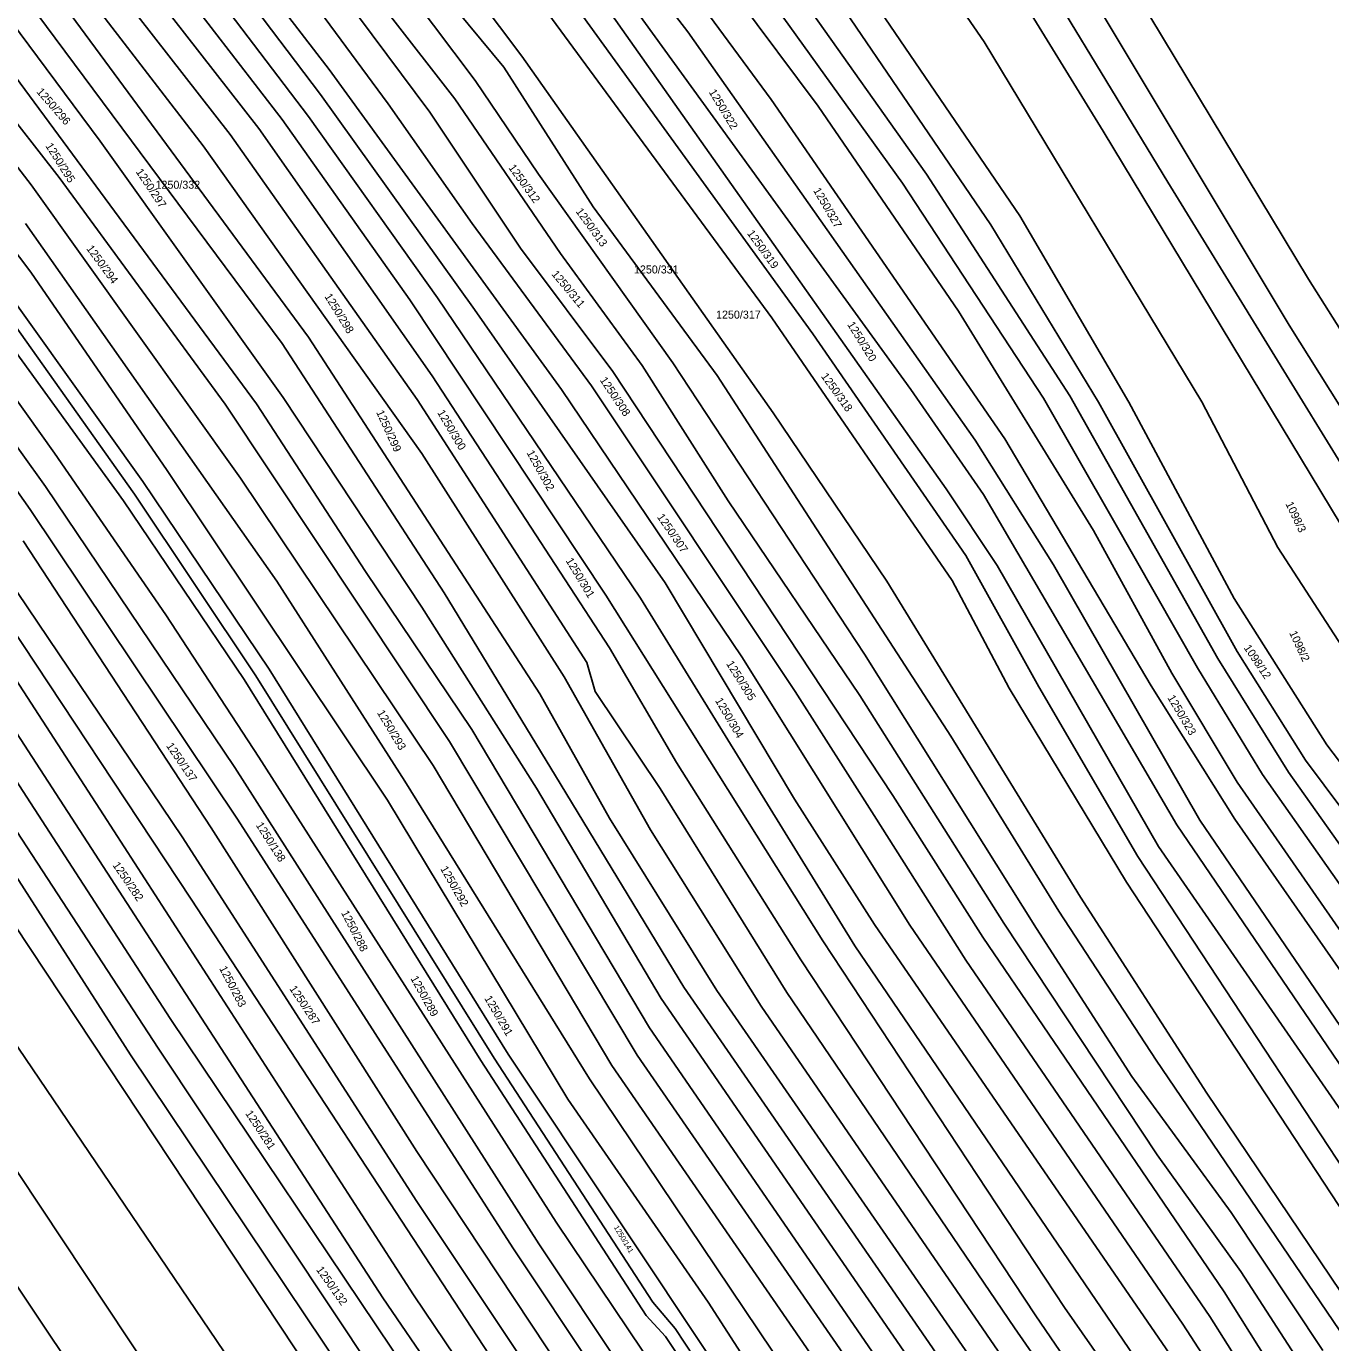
# Model space of a CAD drawing. Extents: x -580630 to -576196, y -1189024 to -1183567.
# Drawn here: x -576696.2 to -576419.3, y -1187029.9 to -1186750.3 of the extents above; entities that cross this region are included whole.
import ezdxf

# ---------------------------------------------------------------- set-up
doc = ezdxf.new("R2010")
doc.units = 0
for name, color, linetype in [('Vrstva 1', 7, 'Continuous'), ('Vrstva 13', 7, 'Continuous'), ('Vrstva 18', 7, 'Continuous'), ('Vrstva 6', 7, 'Continuous')]:
    doc.layers.add(name, color=color, linetype=linetype)

msp = doc.modelspace()

# ---------------------------------------------------------------- linework, layer by layer
at = {"layer": 'Vrstva 1'}
for p, q in [((-576556.97, -1186708.4), (-576505.07, -1186781.72)), ((-576505.07, -1186781.72), (-576474.68, -1186828.83)), ((-576474.68, -1186828.83), (-576443.27, -1186884.64)), ((-576443.27, -1186884.64), (-576428.26, -1186908.73)), ((-576428.26, -1186908.73), (-576403.1, -1186944.3))]:
    msp.add_line(p, q, dxfattribs=at)
at = {"layer": 'Vrstva 13'}
for p in [(-576479.83, -1186711.34), (-576349.23, -1186922.92)]:
    msp.add_line(p, (-576423.97, -1186804.04), dxfattribs=at)
at = {"layer": 'Vrstva 6'}
for p, q in [((-576613.29, -1186682.63), (-576508.42, -1186827.47)), ((-576534.36, -1186692.75), (-576492.88, -1186753.59)), ((-576622.55, -1186696.97), (-576537.97, -1186812.23)), ((-576546.23, -1186701.09), (-576485.28, -1186790.58)), ((-576591.05, -1186756.63), (-576630.49, -1186703.86)), ((-576491.41, -1186792.52), (-576551.36, -1186704.52)), ((-576561.77, -1186711.76), (-576510.17, -1186783.65)), ((-576647.75, -1186718.6), (-576610.52, -1186768.55)), ((-576672.45, -1186721.96), (-576636.33, -1186769.44)), ((-576666.06, -1186722.05), (-576633.75, -1186764.79)), ((-576661.74, -1186720.73), (-576631.94, -1186759.47)), ((-576652.19, -1186722.22), (-576619.42, -1186766.8)), ((-576555.75, -1186751.48), (-576577.57, -1186723.34)), ((-576675.89, -1186726.07), (-576641.91, -1186770.11)), ((-576479.93, -1186727.4), (-576428.06, -1186813.81)), ((-576677.23, -1186732.97), (-576646.86, -1186772.02)), ((-576553.73, -1186732.94), (-576528.12, -1186767.27)), ((-576453.84, -1186783.39), (-576485.53, -1186731.29)), ((-576681.61, -1186736.43), (-576652.92, -1186773.31)), ((-576587.25, -1186735.49), (-576529.24, -1186815.62)), ((-576467.57, -1186772.6), (-576490.49, -1186735.3)), ((-576594.84, -1186759.02), (-576612.67, -1186737.47)), ((-576559.28, -1186736.98), (-576538.08, -1186765.85)), ((-576686.36, -1186739.65), (-576658.67, -1186775.72)), ((-576615.81, -1186741.99), (-576600.9, -1186761.8)), ((-576696.02, -1186744.83), (-576641.92, -1186817.73)), ((-576701.41, -1186746.62), (-576680.56, -1186774.73)), ((-576688.69, -1186745.25), (-576636.34, -1186816.34)), ((-576619.43, -1186747.49), (-576605.22, -1186765.7)), ((-576572.79, -1186746.71), (-576500.9, -1186848.56)), ((-576715.25, -1186749.11), (-576689.28, -1186782.4)), ((-576708.39, -1186747.72), (-576647.39, -1186830.49)), ((-576719.41, -1186752.77), (-576695.21, -1186783.97)), ((-576494.76, -1186838.24), (-576555.75, -1186751.48)), ((-576492.88, -1186753.59), (-576446.62, -1186830.11)), ((-576591.05, -1186756.63), (-576537.67, -1186832.45)), ((-576727.86, -1186759.52), (-576695.31, -1186802.52)), ((-576631.94, -1186759.47), (-576582.63, -1186827.47)), ((-576594.84, -1186759.02), (-576575.89, -1186788.67)), ((-576600.9, -1186761.8), (-576587.49, -1186781.76)), ((-576633.75, -1186764.79), (-576601.07, -1186810.5)), ((-576619.42, -1186766.8), (-576601.59, -1186792.17)), ((-576605.22, -1186765.7), (-576582.84, -1186798.6)), ((-576538.08, -1186765.85), (-576488.46, -1186837.95)), ((-576636.33, -1186769.44), (-576608.94, -1186808)), ((-576610.52, -1186768.55), (-576591.31, -1186797.45)), ((-576528.12, -1186767.27), (-576498.33, -1186810.85)), ((-576739.41, -1186772.11), (-576690.26, -1186841)), ((-576646.86, -1186772.02), (-576610.09, -1186824.59)), ((-576641.91, -1186770.11), (-576614.79, -1186808.4)), ((-576404.7, -1186876.84), (-576467.57, -1186772.6)), ((-576680.56, -1186774.73), (-576641.68, -1186829.18)), ((-576652.92, -1186773.31), (-576613.27, -1186829.57)), ((-576658.67, -1186775.72), (-576612.25, -1186841.03)), ((-576738.63, -1186783.42), (-576692.19, -1186848.05)), ((-576695.21, -1186783.97), (-576650.79, -1186846.3)), ((-576689.28, -1186782.4), (-576654.04, -1186830.6)), ((-576587.49, -1186781.76), (-576558.99, -1186821.8)), ((-576510.17, -1186783.65), (-576480.27, -1186829.33)), ((-576401.55, -1186868.57), (-576453.84, -1186783.39)), ((-576741.86, -1186787.12), (-576695.41, -1186852.99)), ((-576575.89, -1186788.67), (-576549.52, -1186824.52)), ((-576710.52, -1186792.35), (-576671.51, -1186847.01)), ((-576696.44, -1186792.22), (-576643.03, -1186868.21)), ((-576601.59, -1186792.17), (-576576.24, -1186826.72)), ((-576485.28, -1186790.58), (-576462.15, -1186830.15)), ((-576712.79, -1186793.93), (-576673.25, -1186849.73)), ((-576468.58, -1186830.13), (-576491.41, -1186792.52)), ((-576715.59, -1186795.88), (-576675.6, -1186851.14)), ((-576591.31, -1186797.45), (-576571.69, -1186823.66)), ((-576582.84, -1186798.6), (-576565.48, -1186822.38)), ((-576695.31, -1186802.52), (-576666.32, -1186844.69)), ((-576614.79, -1186808.4), (-576573.22, -1186871.14)), ((-576608.94, -1186808), (-576565.85, -1186871.82)), ((-576601.07, -1186810.5), (-576560.58, -1186868.57)), ((-576498.33, -1186810.85), (-576469.67, -1186857.4)), ((-576737.02, -1186812.88), (-576663.12, -1186922.52)), ((-576537.97, -1186812.23), (-576499.65, -1186868.02)), ((-576428.06, -1186813.81), (-576409.16, -1186844.09)), ((-576636.34, -1186816.34), (-576587.21, -1186892.15)), ((-576529.24, -1186815.62), (-576496.74, -1186862.75)), ((-576641.92, -1186817.73), (-576607.52, -1186870.67)), ((-576565.48, -1186822.38), (-576547.18, -1186851.13)), ((-576558.99, -1186821.8), (-576518.26, -1186883.69)), ((-576610.09, -1186824.59), (-576572.4, -1186882.36)), ((-576571.69, -1186823.66), (-576512.27, -1186913.69)), ((-576549.52, -1186824.52), (-576499.95, -1186901.11)), ((-576582.63, -1186827.47), (-576544.28, -1186884.24)), ((-576576.24, -1186826.72), (-576532.98, -1186891.59)), ((-576508.42, -1186827.47), (-576492.98, -1186849.76)), ((-576654.04, -1186830.6), (-576606.37, -1186902.22)), ((-576647.39, -1186830.49), (-576624.21, -1186866.12)), ((-576641.68, -1186829.18), (-576612.26, -1186873.73)), ((-576613.27, -1186829.57), (-576577.24, -1186885.49)), ((-576480.27, -1186829.33), (-576465.39, -1186855.28)), ((-576439.15, -1186883.1), (-576468.58, -1186830.13)), ((-576462.15, -1186830.15), (-576439.76, -1186871.85)), ((-576446.62, -1186830.11), (-576430.48, -1186861.01)), ((-576537.67, -1186832.45), (-576513.52, -1186868.21)), ((-576478.15, -1186864.72), (-576494.76, -1186838.24)), ((-576488.46, -1186837.95), (-576457.4, -1186890.42)), ((-576690.26, -1186841), (-576666.59, -1186875.31)), ((-576612.25, -1186841.03), (-576582, -1186888.49)), ((-576666.32, -1186844.69), (-576619.52, -1186914.69)), ((-576692.19, -1186848.05), (-576651.96, -1186907.77)), ((-576671.51, -1186847.01), (-576644.65, -1186886.91)), ((-576650.79, -1186846.3), (-576609.83, -1186907.35)), ((-576673.25, -1186849.73), (-576647.5, -1186888.27)), ((-576500.9, -1186848.56), (-576490.11, -1186864.82)), ((-576492.98, -1186849.76), (-576451.94, -1186919.97)), ((-576695.41, -1186852.99), (-576651.38, -1186918.74)), ((-576675.6, -1186851.14), (-576649.99, -1186889.07)), ((-576547.18, -1186851.13), (-576519.25, -1186892.44)), ((-576465.39, -1186855.28), (-576447.53, -1186886.57)), ((-576469.67, -1186857.4), (-576453.04, -1186887.69)), ((-576711.3, -1186860), (-576661.21, -1186935.74)), ((-576696.89, -1186859.62), (-576657.02, -1186920.57)), ((-576430.48, -1186861.01), (-576413.37, -1186887.43)), ((-576715.41, -1186862.97), (-576679.88, -1186917.85)), ((-576496.74, -1186862.75), (-576481.27, -1186890.65)), ((-576490.11, -1186864.82), (-576455.83, -1186924.53)), ((-576447.09, -1186918.98), (-576478.15, -1186864.72)), ((-576720.45, -1186866.31), (-576620.55, -1187020.4)), ((-576624.21, -1186866.12), (-576601.63, -1186899.67)), ((-576724.98, -1186869.58), (-576665.68, -1186961.07)), ((-576643.03, -1186868.21), (-576615.86, -1186910.69)), ((-576607.52, -1186870.67), (-576583.85, -1186909.5)), ((-576560.58, -1186868.57), (-576533.11, -1186914.46)), ((-576513.52, -1186868.21), (-576472.4, -1186935.3)), ((-576499.65, -1186868.02), (-576487.56, -1186890.9)), ((-576573.22, -1186871.14), (-576527.14, -1186944.61)), ((-576565.85, -1186871.82), (-576520.29, -1186945.68)), ((-576439.76, -1186871.85), (-576420.11, -1186902.97)), ((-576666.59, -1186875.31), (-576646.89, -1186905.55)), ((-576612.26, -1186873.73), (-576587.88, -1186912.15)), ((-576732.19, -1186878.22), (-576674.14, -1186968.77)), ((-576727.06, -1186877.22), (-576668.24, -1186967.37)), ((-576572.4, -1186882.36), (-576558.19, -1186906.7)), ((-576544.28, -1186884.24), (-576508.63, -1186941.28)), ((-576518.26, -1186883.69), (-576481.76, -1186941.93)), ((-576424.6, -1186906.19), (-576439.15, -1186883.1)), ((-576644.65, -1186886.91), (-576593.89, -1186968.68)), ((-576577.24, -1186885.49), (-576575.47, -1186891.62)), ((-576447.53, -1186886.57), (-576433.75, -1186909.28)), ((-576649.99, -1186889.07), (-576599.72, -1186969.97)), ((-576647.5, -1186888.27), (-576596.89, -1186969.49)), ((-576582, -1186888.49), (-576563.71, -1186921.02)), ((-576453.04, -1186887.69), (-576439.15, -1186910.91)), ((-576587.21, -1186892.15), (-576572.43, -1186918.51)), ((-576575.47, -1186891.62), (-576561.64, -1186912.25)), ((-576532.98, -1186891.59), (-576516.19, -1186917.96)), ((-576519.25, -1186892.44), (-576488.71, -1186940.84)), ((-576487.56, -1186890.9), (-576462.64, -1186932.11)), ((-576481.27, -1186890.65), (-576460.21, -1186926.68)), ((-576457.4, -1186890.42), (-576439.62, -1186918.74)), ((-576601.63, -1186899.67), (-576563.93, -1186963.08)), ((-576499.95, -1186901.11), (-576477.02, -1186938.27)), ((-576606.37, -1186902.22), (-576566.5, -1186968.88)), ((-576420.11, -1186902.97), (-576397.3, -1186933.05)), ((-576646.89, -1186905.55), (-576583.76, -1187004.36)), ((-576558.19, -1186906.7), (-576531.75, -1186948.6)), ((-576398.86, -1186940.88), (-576424.6, -1186906.19)), ((-576651.96, -1186907.77), (-576587.41, -1187008.97)), ((-576609.83, -1186907.35), (-576571.93, -1186971.05)), ((-576583.85, -1186909.5), (-576556.6, -1186954.42)), ((-576408.69, -1186944.93), (-576433.75, -1186909.28)), ((-576615.86, -1186910.69), (-576576.68, -1186973.9)), ((-576587.88, -1186912.15), (-576561.43, -1186956.81)), ((-576561.64, -1186912.25), (-576534.73, -1186955.58)), ((-576439.15, -1186910.91), (-576411.01, -1186951.43)), ((-576619.52, -1186914.69), (-576581.26, -1186978.2)), ((-576533.11, -1186914.46), (-576516.12, -1186941.13)), ((-576512.27, -1186913.69), (-576493.15, -1186943.79)), ((-576679.88, -1186917.85), (-576614.03, -1187019.76)), ((-576516.19, -1186917.96), (-576496.78, -1186948.72)), ((-576657.02, -1186920.57), (-576613.32, -1186989.34)), ((-576651.38, -1186918.74), (-576592.95, -1187009.79)), ((-576572.43, -1186918.51), (-576549.62, -1186955.14)), ((-576451.94, -1186919.97), (-576411.98, -1186978.75)), ((-576447.09, -1186918.98), (-576405.8, -1186979.52)), ((-576439.62, -1186918.74), (-576416.04, -1186952.56)), ((-576663.12, -1186922.52), (-576613.34, -1186999.97)), ((-576563.71, -1186921.02), (-576540.2, -1186958.46)), ((-576455.83, -1186924.53), (-576417.04, -1186980.67)), ((-576460.21, -1186926.68), (-576400.41, -1187017.72)), ((-576462.64, -1186932.11), (-576403.1, -1187022.91)), ((-576702.16, -1186936.16), (-576606.46, -1187080.61)), ((-576661.21, -1186935.74), (-576571.39, -1187073.1)), ((-576472.4, -1186935.3), (-576445.56, -1186976.91)), ((-576477.02, -1186938.27), (-576456.31, -1186969.94)), ((-576714.28, -1186943.27), (-576635.3, -1187059.84)), ((-576451.12, -1187035.8), (-576516.12, -1186941.13)), ((-576508.63, -1186941.28), (-576450.65, -1187026)), ((-576488.71, -1186940.84), (-576456.11, -1186990.05)), ((-576481.76, -1186941.93), (-576461.52, -1186973.42)), ((-576527.14, -1186944.61), (-576475.79, -1187022.47)), ((-576429.1, -1187079.72), (-576520.29, -1186945.68)), ((-576493.15, -1186943.79), (-576441.9, -1187019.13)), ((-576531.75, -1186948.6), (-576481.89, -1187024.23)), ((-576496.78, -1186948.72), (-576444.96, -1187024.35)), ((-576725.88, -1186951.87), (-576663.87, -1187045.28)), ((-576556.6, -1186954.42), (-576481.91, -1187062.75)), ((-576561.43, -1186956.81), (-576460.53, -1187103.46)), ((-576549.62, -1186955.14), (-576476.18, -1187061.4)), ((-576534.73, -1186955.58), (-576486.44, -1187026.79)), ((-576540.2, -1186958.46), (-576485.43, -1187038.17)), ((-576735.59, -1186962.22), (-576664.28, -1187068.51)), ((-576665.68, -1186961.07), (-576595.31, -1187065.98)), ((-576563.93, -1186963.08), (-576465.13, -1187106.78)), ((-576668.24, -1186967.37), (-576619.48, -1187040.76)), ((-576674.14, -1186968.77), (-576615.76, -1187055.87)), ((-576599.72, -1186969.97), (-576564.62, -1187024.17)), ((-576596.89, -1186969.49), (-576563.19, -1187021.36)), ((-576593.89, -1186968.68), (-576489.64, -1187125.26)), ((-576571.93, -1186971.05), (-576520.99, -1187044.93)), ((-576566.5, -1186968.88), (-576515.47, -1187042.87)), ((-576456.31, -1186969.94), (-576416.1, -1187029.22)), ((-576576.68, -1186973.9), (-576526.06, -1187049.15)), ((-576461.52, -1186973.42), (-576440.44, -1187002.31)), ((-576445.56, -1186976.91), (-576415.02, -1187022.34)), ((-576581.26, -1186978.2), (-576551.45, -1187021.36)), ((-576613.32, -1186989.34), (-576544.98, -1187092.41)), ((-576456.11, -1186990.05), (-576438.37, -1187014.84)), ((-576613.34, -1186999.97), (-576549.71, -1187095.36)), ((-576583.76, -1187004.36), (-576533.37, -1187079.24)), ((-576440.44, -1187002.31), (-576420.95, -1187031.58)), ((-576592.95, -1187009.79), (-576541.08, -1187087.43)), ((-576587.41, -1187008.97), (-576537.42, -1187084.06)), ((-576438.37, -1187014.84), (-576422.96, -1187038.55)), ((-576620.55, -1187020.4), (-576581.36, -1187077.51)), ((-576614.03, -1187019.76), (-576577.14, -1187074.53)), ((-576563.19, -1187021.36), (-576558.46, -1187026.96)), ((-576551.45, -1187021.36), (-576510.26, -1187085.01)), ((-576441.9, -1187019.13), (-576411.74, -1187067.05)), ((-576564.62, -1187024.17), (-576560.53, -1187028.64)), ((-576481.89, -1187024.23), (-576439.09, -1187086.94)), ((-576475.79, -1187022.47), (-576433.56, -1187082.94)), ((-576444.96, -1187024.35), (-576416.01, -1187070.12)), ((-576558.46, -1187026.96), (-576491.88, -1187126.87)), ((-576486.44, -1187026.79), (-576442.57, -1187089.6)), ((-576450.65, -1187026), (-576420.11, -1187073.22)), ((-576560.53, -1187028.64), (-576527.68, -1187077.63))]:
    msp.add_line(p, q, dxfattribs=at)

# ---------------------------------------------------------------- texts
at = {"layer": 'Vrstva 18'}
for s, height, rotation, p in [('1250/296', 1.7, 310.8869, (-576694.168, -1186764.287)), ('1250/322', 1.7, 301.08932, (-576551.378, -1186764.28)), ('1250/295', 1.7, 302.29253, (-576692.236, -1186775.728)), ('1250/297', 1.7, 303.83952, (-576673.06, -1186781.23)), ('1250/312', 1.7, 305.90217, (-576593.938, -1186780.368)), ('1250/327', 1.7, 300.28718, (-576529.214, -1186785.179)), ('1250/313', 1.7, 305.90217, (-576579.656, -1186789.648)), ('1250/319', 1.7, 305.95946, (-576543.279, -1186794.321)), ('1250/294', 1.7, 306.24594, (-576683.577, -1186797.546)), ('1250/311', 1.7, 309.62639, (-576584.802, -1186803.007)), ('1250/298', 1.7, 301.66228, (-576632.991, -1186807.689)), ('1250/320', 1.7, 301.66228, (-576521.981, -1186813.659)), ('1250/308', 1.7, 303.78222, (-576574.532, -1186825.473)), ('1250/318', 1.7, 305.73028, (-576527.575, -1186824.683)), ('1250/299', 1.7, 294.44301, (-576621.984, -1186832.288)), ('1250/300', 1.7, 300.45907, (-576609.028, -1186832.37)), ('1250/302', 1.7, 298.96938, (-576590.058, -1186840.909)), ('1098/3', 1.7, 295.41704, (-576428.91, -1186851.754)), ('1250/307', 1.7, 304.46977, (-576562.391, -1186854.55)), ('1250/301', 1.7, 301.03202, (-576581.772, -1186863.819)), ('1098/2', 1.7, 294.95867, (-576428.116, -1186879.183)), ('1098/12', 1.7, 304.01141, (-576437.803, -1186882.353)), ('1250/305', 1.7, 302.12064, (-576547.694, -1186885.725)), ('1250/304', 1.7, 300.34447, (-576550.045, -1186893.538)), ('1250/323', 1.7, 300.57366, (-576453.992, -1186892.953)), ('1250/293', 1.7, 300.97473, (-576621.821, -1186896.138)), ('1250/137', 1.7, 304.29789, (-576666.607, -1186903.18)), ('1250/138', 1.7, 302.46442, (-576647.566, -1186920.011)), ('1250/282', 1.7, 304.35518, (-576677.989, -1186928.521)), ('1250/292', 1.7, 299.54234, (-576608.386, -1186929.261)), ('1250/288', 1.7, 297.07862, (-576629.428, -1186938.633)), ('1250/283', 1.7, 297.47969, (-576655.322, -1186950.441)), ('1250/287', 1.7, 303.66763, (-576640.442, -1186954.759)), ('1250/289', 1.7, 298.85479, (-576614.706, -1186952.57)), ('1250/291', 1.7, 300.17259, (-576599.036, -1186956.795)), ('1250/281', 1.7, 303.43845, (-576649.814, -1186981.254)), ('1250/141', 1.14, 300.91743, (-576571.536, -1187005.441)), ('1250/132', 1.7, 305.15732, (-576634.764, -1187014.45))]:
    msp.add_text(s, height=height, rotation=rotation, dxfattribs=at).set_placement(p)
for s, p in [('1250/332', (-576668.798, -1186784.82)), ('1250/331', (-576567.216, -1186802.82)), ('1250/317', (-576549.779, -1186812.41))]:
    msp.add_text(s, height=1.7, dxfattribs=at).set_placement(p)

doc.saveas('drawing.dxf')
